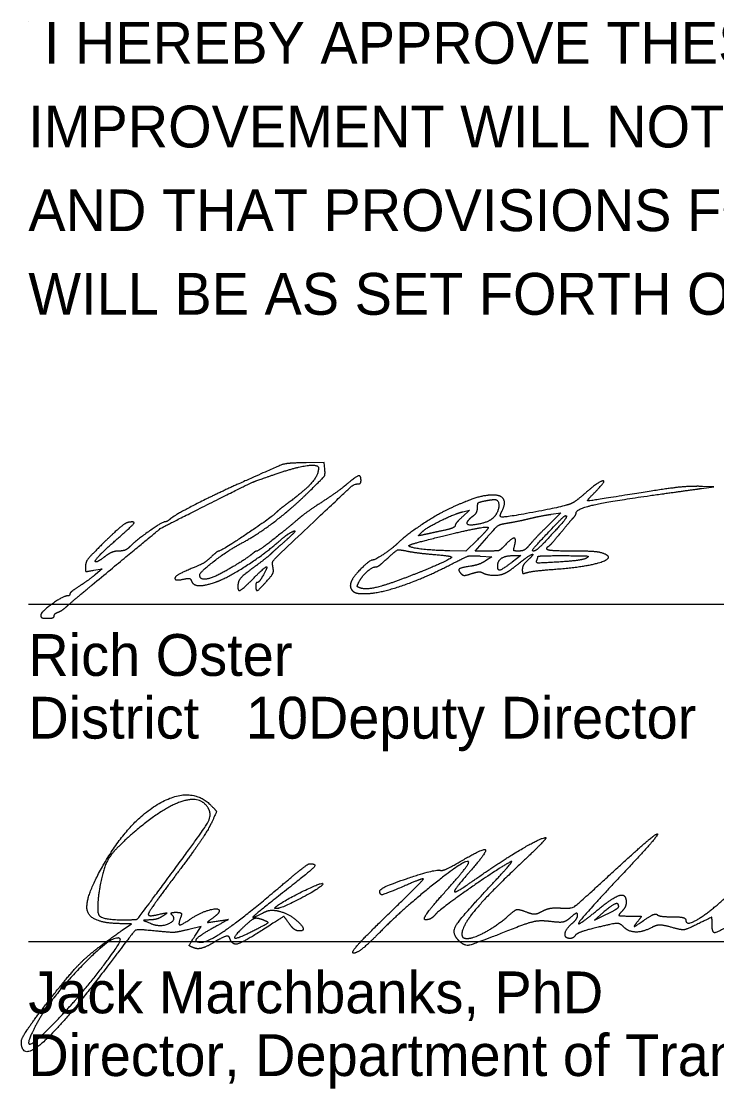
# Model space of a CAD drawing. Extents: x 0 to 34, y 0 to 22.
# Drawn here: x 24.504 to 26.833, y 7.305 to 10.877 of the extents above; entities that cross this region are included whole.
import ezdxf

# ---------------------------------------------------------------- set-up
doc = ezdxf.new("R2010")
doc.units = 0
doc.layers.add('SH_Data', color=7, linetype='Continuous')
doc.layers.add('SH_Text', color=7, linetype='Continuous')

msp = doc.modelspace()

# ---------------------------------------------------------------- linework, layer by layer
at = {"layer": 'SH_Data'}
for p, q in [((24.5279, 10.875), (24.5279, 10.875)), ((24.5279, 8.9262), (28.0279, 8.9262)), ((24.5279, 7.7968), (28.0279, 7.7968))]:
    msp.add_line(p, q, dxfattribs=at)
at = {"layer": 'SH_Text'}
for p, q in [((24.5693, 8.8891), (24.5693, 8.8891)), ((24.9902, 8.0019), (24.9902, 8.0019)), ((25.3555, 7.912), (25.3555, 7.912)), ((26.5045, 7.914), (26.5045, 7.914)), ((25.3107, 7.8703), (25.3107, 7.8703)), ((25.7273, 7.883), (25.7273, 7.883))]:
    msp.add_line(p, q, dxfattribs=at)
for points in [[(25.5205, 9.3784), (25.518, 9.4002), (25.458, 9.3995)], [(26.7818, 9.3137), (26.823, 9.3195), (26.7853, 9.3205)], [(25.9831, 9.2356), (26.0055, 9.2409), (25.9812, 9.2186)], [(26.2781, 9.2271), (26.3106, 9.2318), (26.2668, 9.1885)], [(26.0643, 9.104), (26.0234, 9.104), (26.0626, 9.1485)], [(26.0316, 9.1419), (25.9924, 9.104), (25.9389, 9.1049)], [(26.0409, 9.0875), (26.0801, 9.0852), (26.0587, 9.0712)], [(26.1518, 9.089), (26.177, 9.089), (26.1475, 9.0667)], [(24.7474, 9.0398), (24.7755, 9.0447), (24.753, 9.0259)], [(26.4527, 7.8943), (26.4232, 7.8687), (26.4638, 7.8884)], [(24.8425, 7.8349), (24.8732, 7.8561), (24.8354, 7.8568)], [(25.0855, 7.8151), (25.1067, 7.8474), (25.0649, 7.8373)]]:
    msp.add_lwpolyline(points, dxfattribs=at)
for points in [[(25.458, 9.3995), (25.3955, 9.3988), (25.3691, 9.3906), (25.233, 9.3295)], [(25.1505, 9.2712), (25.2627, 9.3275), (25.2883, 9.3388), (25.3605, 9.3634)], [(25.3605, 9.3634), (25.4246, 9.3853), (25.4993, 9.3953), (25.4993, 9.382)], [(25.4993, 9.382), (25.4993, 9.3581), (25.4543, 9.3067), (25.3951, 9.2632)], [(25.4605, 9.2959), (25.5145, 9.3482), (25.5227, 9.3595), (25.5205, 9.3784)], [(25.233, 9.3295), (25.1528, 9.2934), (25.017, 9.2238), (25.0037, 9.212)], [(25.3754, 9.0998), (25.5968, 9.3094), (25.6188, 9.3289), (25.6324, 9.3289)], [(25.5925, 9.3265), (25.5763, 9.3128), (25.5394, 9.2864), (25.5105, 9.2677)], [(25.6418, 9.3402), (25.6418, 9.3582), (25.6242, 9.3533), (25.5925, 9.3265)], [(25.6324, 9.3289), (25.6376, 9.3289), (25.6418, 9.334), (25.6418, 9.3402)], [(26.4286, 9.3046), (26.4654, 9.3414), (26.4359, 9.3361), (26.3929, 9.2981)], [(25.2372, 9.128), (25.2909, 9.1564), (25.4056, 9.2426), (25.4605, 9.2959)], [(26.0844, 9.2915), (26.0569, 9.2915), (25.9951, 9.2723), (25.9396, 9.2466)], [(26.1144, 9.2392), (26.1272, 9.2631), (26.1109, 9.2915), (26.0844, 9.2915)], [(26.3929, 9.2981), (26.3737, 9.2812), (26.3513, 9.2648), (26.343, 9.2618)], [(26.3618, 9.2311), (26.3618, 9.2455), (26.4844, 9.2727), (26.6551, 9.2961)], [(26.5253, 9.2906), (26.4049, 9.2711), (26.3963, 9.2723), (26.4286, 9.3046)], [(26.7853, 9.3205), (26.7409, 9.3216), (26.657, 9.312), (26.5253, 9.2906)], [(26.6551, 9.2961), (26.7021, 9.3026), (26.7591, 9.3105), (26.7818, 9.3137)], [(24.7418, 8.991), (24.9664, 9.177), (24.9759, 9.1835), (25.1505, 9.2712)], [(25.3951, 9.2632), (25.3802, 9.2522), (25.3621, 9.2373), (25.3548, 9.2301)], [(25.5105, 9.2677), (25.4817, 9.2491), (25.4479, 9.2251), (25.4355, 9.2145)], [(26.0318, 9.2497), (26.0318, 9.2632), (26.0371, 9.2681), (26.0552, 9.2718)], [(26.0552, 9.2718), (26.0681, 9.2743), (26.0833, 9.2765), (26.089, 9.2765)], [(26.089, 9.2765), (26.104, 9.2765), (26.102, 9.2337), (26.0862, 9.217)], [(26.343, 9.2618), (26.3157, 9.2517), (26.1139, 9.2143), (26.1097, 9.2185)], [(25.3548, 9.2301), (25.34, 9.2152), (25.1732, 9.104), (25.1659, 9.104)], [(25.9396, 9.2466), (25.8976, 9.2272), (25.7891, 9.1548), (25.7634, 9.1291)], [(25.8443, 9.1662), (25.8587, 9.1811), (25.9538, 9.2286), (25.9831, 9.2356)], [(25.9812, 9.2186), (25.9678, 9.2064), (25.9568, 9.193), (25.9568, 9.1888)], [(25.9985, 9.2025), (26.0019, 9.2081), (26.0107, 9.2171), (26.0182, 9.2225)], [(26.0182, 9.2225), (26.0257, 9.2279), (26.0318, 9.2401), (26.0318, 9.2497)], [(26.1097, 9.2185), (26.1074, 9.2208), (26.1096, 9.2301), (26.1144, 9.2392)], [(26.2043, 9.2126), (26.227, 9.218), (26.2602, 9.2245), (26.2781, 9.2271)], [(26.3288, 9.222), (26.3322, 9.2185), (26.3084, 9.1895), (26.2558, 9.1331)], [(26.3042, 9.2034), (26.3158, 9.2155), (26.3268, 9.2239), (26.3288, 9.222)], [(26.3524, 9.2151), (26.3576, 9.2206), (26.3618, 9.2277), (26.3618, 9.2311)], [(24.8621, 9.2001), (24.8541, 9.1988), (24.8186, 9.1694), (24.7834, 9.1349)], [(24.8524, 9.1685), (24.8801, 9.1927), (24.8835, 9.2036), (24.8621, 9.2001)], [(24.9846, 9.2015), (24.9759, 9.2015), (24.8862, 9.1376), (24.8671, 9.1179)], [(25.0037, 9.212), (24.9972, 9.2062), (24.9886, 9.2015), (24.9846, 9.2015)], [(25.4355, 9.2145), (25.3909, 9.1761), (25.2982, 9.104), (25.2935, 9.104)], [(25.8571, 9.1396), (25.9539, 9.1644), (26.0634, 9.1873), (26.0672, 9.1835)], [(25.9568, 9.1888), (25.9568, 9.1847), (25.9374, 9.1771), (25.9137, 9.172)], [(26.0862, 9.217), (26.0698, 9.1997), (25.9888, 9.1863), (25.9985, 9.2025)], [(26.0672, 9.1835), (26.0692, 9.1816), (26.0531, 9.1628), (26.0316, 9.1419)], [(26.0626, 9.1485), (26.095, 9.1853), (26.1072, 9.1939), (26.1324, 9.1979)], [(26.1324, 9.1979), (26.1493, 9.2005), (26.1816, 9.2071), (26.2043, 9.2126)], [(26.2668, 9.1885), (26.2428, 9.1646), (26.2155, 9.1359), (26.2062, 9.1245)], [(26.2196, 9.104), (26.2118, 9.104), (26.2332, 9.1291), (26.3042, 9.2034)], [(26.3093, 9.164), (26.3278, 9.1866), (26.3472, 9.2097), (26.3524, 9.2151)], [(24.7524, 9.0683), (24.7487, 9.072), (24.7956, 9.119), (24.8524, 9.1685)], [(25.3643, 9.1342), (25.3787, 9.1469), (25.3969, 9.1608), (25.4046, 9.1651)], [(25.4046, 9.1651), (25.4253, 9.1767), (25.4127, 9.159), (25.3802, 9.1307)], [(25.8518, 9.1586), (25.835, 9.155), (25.8342, 9.1558), (25.8443, 9.1662)], [(25.9137, 9.172), (25.8899, 9.1669), (25.8621, 9.1608), (25.8518, 9.1586)], [(26.1562, 9.1227), (26.1624, 9.1474), (26.1464, 9.1474), (26.1229, 9.1226)], [(26.2699, 9.1202), (26.273, 9.1216), (26.2907, 9.1413), (26.3093, 9.164)], [(24.7834, 9.1349), (24.737, 9.0894), (24.7193, 9.0669), (24.7193, 9.0534)], [(24.8671, 9.1179), (24.8597, 9.1102), (24.8435, 9.104), (24.831, 9.104)], [(25.1018, 9.024), (25.1018, 9.0335), (25.1976, 9.1071), (25.2372, 9.128)], [(25.155, 9.0002), (25.1921, 9.013), (25.3186, 9.094), (25.3643, 9.1342)], [(25.3802, 9.1307), (25.3656, 9.1181), (25.348, 9.1022), (25.3411, 9.0955)], [(25.7634, 9.1291), (25.7481, 9.1138), (25.6888, 9.074), (25.6813, 9.074)], [(25.8022, 9.121), (25.8002, 9.123), (25.8249, 9.1314), (25.8571, 9.1396)], [(25.9389, 9.1049), (25.8837, 9.1059), (25.8085, 9.1147), (25.8022, 9.121)], [(26.1229, 9.1226), (26.1083, 9.1072), (26.0981, 9.104), (26.0643, 9.104)], [(26.1704, 9.104), (26.154, 9.104), (26.1521, 9.1064), (26.1562, 9.1227)], [(26.2062, 9.1245), (26.1959, 9.112), (26.182, 9.104), (26.1704, 9.104)], [(26.2558, 9.1331), (26.2408, 9.1171), (26.2245, 9.104), (26.2196, 9.104)], [(26.2643, 9.1108), (26.2643, 9.1146), (26.2668, 9.1188), (26.2699, 9.1202)], [(26.3449, 9.1038), (26.3006, 9.1039), (26.2643, 9.107), (26.2643, 9.1108)], [(24.7823, 9.0842), (24.7681, 9.0733), (24.7546, 9.0661), (24.7524, 9.0683)], [(24.831, 9.104), (24.818, 9.104), (24.7972, 9.0955), (24.7823, 9.0842)], [(25.1409, 9.0852), (25.1217, 9.0674), (25.1072, 9.0594), (25.0512, 9.0356)], [(25.1659, 9.104), (25.1633, 9.104), (25.152, 9.0955), (25.1409, 9.0852)], [(25.2796, 9.0963), (25.265, 9.084), (25.2172, 9.0535), (25.1804, 9.033)], [(25.2935, 9.104), (25.2908, 9.104), (25.2846, 9.1005), (25.2796, 9.0963)], [(25.3411, 9.0955), (25.3342, 9.0888), (25.3097, 9.0693), (25.2867, 9.0523)], [(25.347, 9.0502), (25.3441, 9.0655), (25.3498, 9.0755), (25.3754, 9.0998)], [(25.7135, 9.0647), (25.7577, 9.1049), (25.7686, 9.11), (25.7974, 9.1038)], [(25.9443, 9.0819), (25.9348, 9.0738), (25.8329, 9.03), (25.7693, 9.0066)], [(25.7974, 9.1038), (25.8129, 9.1005), (25.8537, 9.0954), (25.8881, 9.0925)], [(25.8881, 9.0925), (25.9225, 9.0896), (25.9478, 9.0849), (25.9443, 9.0819)], [(25.9586, 9.0673), (25.9934, 9.0855), (26.0091, 9.0893), (26.0409, 9.0875)], [(26.0993, 9.054), (26.0993, 9.0714), (26.1257, 9.089), (26.1518, 9.089)], [(26.1728, 9.0645), (26.2054, 9.0909), (26.2247, 9.0955), (26.1968, 9.0702)], [(26.2304, 9.0726), (26.2326, 9.0781), (26.2343, 9.0841), (26.2343, 9.0858)], [(26.2343, 9.0858), (26.2343, 9.0875), (26.2739, 9.0888), (26.3224, 9.0887)], [(26.2943, 9.0436), (26.4055, 9.0522), (26.4942, 9.0854), (26.4427, 9.0991)], [(26.3965, 9.0804), (26.3888, 9.0759), (26.3474, 9.07), (26.3045, 9.0674)], [(26.3224, 9.0887), (26.3895, 9.0885), (26.4072, 9.0865), (26.3965, 9.0804)], [(26.4427, 9.0991), (26.4333, 9.1017), (26.3893, 9.1038), (26.3449, 9.1038)], [(24.7193, 9.0534), (24.7193, 9.036), (24.7211, 9.0351), (24.7474, 9.0398)], [(25.2867, 9.0523), (25.2468, 9.0228), (25.2293, 9.0021), (25.2293, 8.9844)], [(25.2792, 9.0102), (25.3176, 9.0491), (25.3317, 9.0538), (25.3133, 9.0215)], [(25.3267, 9.0037), (25.3443, 9.0238), (25.3497, 9.0361), (25.347, 9.0502)], [(25.6813, 9.074), (25.6704, 9.074), (25.6133, 9.0155), (25.608, 8.9989)], [(25.6353, 9.0014), (25.645, 9.0202), (25.6793, 9.0508), (25.691, 9.0512)], [(25.6524, 8.9615), (25.702, 8.9615), (25.8613, 9.0165), (25.9586, 9.0673)], [(25.691, 9.0512), (25.6954, 9.0513), (25.7055, 9.0574), (25.7135, 9.0647)], [(26.0081, 9.0533), (25.9766, 9.0491), (25.9656, 9.0397), (25.9778, 9.0275)], [(26.0587, 9.0712), (26.0469, 9.0635), (26.0241, 9.0555), (26.0081, 9.0533)], [(26.1475, 9.0667), (26.1155, 9.0425), (26.0993, 9.0382), (26.0993, 9.054)], [(26.1255, 9.0309), (26.1338, 9.035), (26.1551, 9.0502), (26.1728, 9.0645)], [(26.1968, 9.0702), (26.1886, 9.0628), (26.1818, 9.05), (26.1818, 9.0419)], [(26.1818, 9.0419), (26.1818, 9.0301), (26.1851, 9.0282), (26.1987, 9.0324)], [(26.1987, 9.0324), (26.2079, 9.0352), (26.251, 9.0403), (26.2943, 9.0436)], [(26.3045, 9.0674), (26.241, 9.0634), (26.2273, 9.0644), (26.2304, 9.0726)], [(24.753, 9.0259), (24.7407, 9.0155), (24.7162, 8.9978), (24.6987, 8.9865)], [(25.0512, 9.0356), (25.0199, 9.0224), (25.0178, 9.0033), (25.0483, 9.01)], [(25.0483, 9.01), (25.064, 9.0134), (25.0711, 9.0116), (25.0744, 9.0031)], [(25.0744, 9.0031), (25.0798, 8.989), (25.1185, 8.9877), (25.155, 9.0002)], [(25.1804, 9.033), (25.1433, 9.0123), (25.1018, 9.0075), (25.1018, 9.024)], [(25.2293, 8.9844), (25.2293, 8.9683), (25.2468, 8.9773), (25.2792, 9.0102)], [(25.2893, 8.9877), (25.2893, 8.9695), (25.3011, 8.9746), (25.3267, 9.0037)], [(25.3133, 9.0215), (25.3063, 9.0091), (25.298, 8.999), (25.2949, 8.999)], [(25.7693, 9.0066), (25.712, 8.9856), (25.653, 8.9744), (25.6362, 8.9813)], [(25.9778, 9.0275), (25.983, 9.0223), (25.994, 9.0227), (26.0122, 9.0287)], [(26.0122, 9.0287), (26.0269, 9.0335), (26.0429, 9.0351), (26.0476, 9.0322)], [(26.0476, 9.0322), (26.0617, 9.0235), (26.1094, 9.0227), (26.1255, 9.0309)], [(24.6593, 8.9212), (24.6696, 8.9306), (24.7067, 8.962), (24.7418, 8.991)], [(24.6987, 8.9865), (24.6811, 8.9752), (24.6668, 8.9633), (24.6668, 8.96)], [(25.2949, 8.999), (25.2918, 8.999), (25.2893, 8.9939), (25.2893, 8.9877)], [(25.608, 8.9989), (25.6053, 8.9903), (25.6071, 8.9783), (25.6121, 8.9723)], [(25.6121, 8.9723), (25.6173, 8.966), (25.6342, 8.9615), (25.6524, 8.9615)], [(25.6362, 8.9813), (25.6291, 8.9842), (25.6289, 8.989), (25.6353, 9.0014)], [(24.6592, 8.954), (24.645, 8.954), (24.5693, 8.8994), (24.5693, 8.8891)], [(24.6668, 8.96), (24.6668, 8.9567), (24.6634, 8.954), (24.6592, 8.954)], [(24.6143, 8.8867), (24.6143, 8.8909), (24.6202, 8.8966), (24.6274, 8.8993)], [(24.6274, 8.8993), (24.6346, 8.902), (24.649, 8.9119), (24.6593, 8.9212)], [(24.5693, 8.8891), (24.5693, 8.8828), (24.5778, 8.879), (24.5918, 8.879)], [(24.5918, 8.879), (24.6042, 8.879), (24.6143, 8.8824), (24.6143, 8.8867)], [(24.7789, 8.0526), (24.8651, 8.203), (25.0732, 8.319), (25.1389, 8.2534)], [(25.1299, 8.2442), (25.104, 8.2862), (24.9779, 8.245), (24.8825, 8.1634)], [(25.1389, 8.2534), (25.1577, 8.2346), (25.1577, 8.2295), (25.1394, 8.1911)], [(24.9902, 8.0019), (25.1115, 8.1653), (25.144, 8.2215), (25.1299, 8.2442)], [(25.1394, 8.1911), (25.1284, 8.1681), (25.0767, 8.0926), (25.0245, 8.0232)], [(24.8825, 8.1634), (24.8159, 8.1064), (24.7771, 8.0423), (24.766, 7.971)], [(26.4869, 8.0315), (26.5619, 8.1006), (26.6279, 8.1572), (26.6336, 8.1573)], [(26.6336, 8.1573), (26.6394, 8.1574), (26.5873, 8.0972), (26.518, 8.0236)], [(26.0326, 8.0111), (26.1131, 8.0677), (26.2445, 8.1449), (26.2602, 8.1449)], [(26.2602, 8.1449), (26.265, 8.1449), (26.2237, 8.1023), (26.1684, 8.0502)], [(25.9736, 8.0646), (26.0524, 8.1108), (26.0646, 8.0975), (26.0054, 8.0302)], [(24.8354, 7.8568), (24.7375, 7.8585), (24.7141, 7.9396), (24.7789, 8.0526)], [(25.369, 7.9791), (25.4194, 8.022), (25.4649, 8.0571), (25.4701, 8.0573)], [(25.4701, 8.0573), (25.495, 8.0578), (25.4716, 8.0322), (25.3857, 7.9649)], [(26.0017, 8.0644), (25.9921, 8.074), (25.7824, 7.907), (25.7045, 7.8278)], [(26.142, 8.0639), (26.0929, 8.0361), (25.9046, 7.9039), (25.8914, 7.888)], [(25.908, 8.0354), (25.9136, 8.0335), (25.9431, 8.0467), (25.9736, 8.0646)], [(25.9239, 7.964), (25.9702, 8.0157), (26.0052, 8.0609), (26.0017, 8.0644)], [(26.1684, 8.0502), (26.0687, 7.9565), (25.9795, 7.8484), (25.9795, 7.8214)], [(26.0768, 7.985), (26.123, 8.0342), (26.1523, 8.0697), (26.142, 8.0639)], [(25.0245, 8.0232), (24.9722, 7.9539), (24.9295, 7.8932), (24.9295, 7.8884)], [(25.7047, 7.9668), (25.7049, 7.9774), (25.8923, 8.0405), (25.908, 8.0354)], [(25.7273, 7.883), (25.7983, 7.9514), (25.8537, 8.0074), (25.8502, 8.0074)], [(25.8502, 8.0074), (25.8468, 8.0074), (25.8178, 7.9962), (25.7857, 7.9824)], [(26.0054, 8.0302), (25.9774, 7.9984), (25.9545, 7.9687), (25.9545, 7.9643)], [(25.9545, 7.9643), (25.9545, 7.9598), (25.9896, 7.9809), (26.0326, 8.0111)], [(26.3119, 7.9091), (26.3453, 7.9063), (26.3688, 7.9227), (26.4869, 8.0315)], [(26.518, 8.0236), (26.3885, 7.8861), (26.3564, 7.8388), (26.4386, 7.9065)], [(24.766, 7.971), (24.7545, 7.8977), (24.776, 7.8699), (24.844, 7.8699)], [(24.844, 7.8699), (24.8907, 7.8699), (24.8953, 7.874), (24.9902, 8.0019)], [(25.1076, 7.7949), (25.1307, 7.7949), (25.2567, 7.8837), (25.369, 7.9791)], [(25.3555, 7.912), (25.3759, 7.9299), (25.5079, 7.9956), (25.5131, 7.9905)], [(25.5131, 7.9905), (25.5193, 7.9843), (25.3767, 7.9074), (25.359, 7.9074)], [(25.7857, 7.9824), (25.7231, 7.9556), (25.7044, 7.952), (25.7047, 7.9668)], [(25.9697, 7.7993), (25.9445, 7.8246), (25.9734, 7.8747), (26.0768, 7.985)], [(26.7295, 7.8684), (26.7295, 7.8456), (26.8248, 7.907), (26.8951, 7.9753)], [(25.3857, 7.9649), (25.2925, 7.8919), (25.271, 7.8704), (25.315, 7.8939)], [(25.8581, 7.8699), (25.8478, 7.8699), (25.8767, 7.9112), (25.9239, 7.964)], [(26.4386, 7.9065), (26.487, 7.9464), (26.5295, 7.9568), (26.5295, 7.9287)], [(25.0736, 7.8743), (25.1025, 7.8941), (25.167, 7.9116), (25.167, 7.8997)], [(25.167, 7.8997), (25.167, 7.8952), (25.1572, 7.8843), (25.1453, 7.8756)], [(25.315, 7.8939), (25.3276, 7.9006), (25.3515, 7.9027), (25.3681, 7.8985)], [(25.359, 7.9074), (25.3542, 7.9074), (25.3526, 7.9095), (25.3555, 7.912)], [(25.3681, 7.8985), (25.4042, 7.8894), (25.4625, 7.8324), (25.4358, 7.8324)], [(26.137, 7.885), (26.1573, 7.903), (26.1701, 7.9056), (26.1939, 7.8966)], [(26.1939, 7.8966), (26.2141, 7.8889), (26.2329, 7.8896), (26.2489, 7.8987)], [(26.2489, 7.8987), (26.2623, 7.9062), (26.2906, 7.9109), (26.3119, 7.9091)], [(26.5045, 7.914), (26.5045, 7.9275), (26.4804, 7.9183), (26.4527, 7.8943)], [(26.4638, 7.8884), (26.4862, 7.8992), (26.5045, 7.9107), (26.5045, 7.914)], [(26.5145, 7.8974), (26.5028, 7.8858), (26.5087, 7.8824), (26.541, 7.8824)], [(26.5295, 7.9287), (26.5295, 7.9198), (26.5227, 7.9057), (26.5145, 7.8974)], [(24.9357, 7.8693), (24.9133, 7.8685), (24.9138, 7.8671), (24.9399, 7.8567)], [(24.9295, 7.8884), (24.9295, 7.8836), (24.9449, 7.8833), (24.9638, 7.8877)], [(24.9795, 7.883), (24.9692, 7.876), (24.9495, 7.8699), (24.9357, 7.8693)], [(24.9399, 7.8567), (24.9698, 7.8447), (25.026, 7.8693), (25.0086, 7.8867)], [(24.9638, 7.8877), (24.9894, 7.8936), (24.9934, 7.8924), (24.9795, 7.883)], [(25.0086, 7.8867), (25.004, 7.8912), (25.0103, 7.8949), (25.0225, 7.8949)], [(25.0225, 7.8949), (25.037, 7.8949), (25.0422, 7.8885), (25.0375, 7.8762)], [(25.0375, 7.8762), (25.0285, 7.8529), (25.0414, 7.8523), (25.0736, 7.8743)], [(25.1453, 7.8756), (25.1264, 7.8618), (25.1284, 7.8605), (25.161, 7.8654)], [(25.161, 7.8654), (25.1977, 7.871), (25.1976, 7.8707), (25.1522, 7.8456)], [(25.3107, 7.8703), (25.2935, 7.8767), (25.277, 7.8716), (25.2576, 7.8538)], [(25.2826, 7.834), (25.329, 7.8577), (25.3325, 7.8623), (25.3107, 7.8703)], [(25.4011, 7.8571), (25.3843, 7.8812), (25.3822, 7.8807), (25.3165, 7.8384)], [(25.617, 7.7581), (25.6067, 7.7583), (25.6563, 7.8145), (25.7273, 7.883)], [(25.8914, 7.888), (25.8831, 7.878), (25.8682, 7.8699), (25.8581, 7.8699)], [(25.9975, 7.8074), (26.0192, 7.8074), (26.1006, 7.8527), (26.137, 7.885)], [(26.2749, 7.864), (26.2457, 7.8677), (26.2058, 7.8612), (26.1693, 7.8468)], [(26.3444, 7.8784), (26.3287, 7.8642), (26.3075, 7.8598), (26.2749, 7.864)], [(26.367, 7.8859), (26.367, 7.893), (26.3568, 7.8896), (26.3444, 7.8784)], [(26.3482, 7.8574), (26.3585, 7.866), (26.367, 7.8788), (26.367, 7.8859)], [(26.541, 7.8824), (26.5785, 7.8824), (26.5809, 7.8804), (26.5654, 7.8611)], [(26.5654, 7.8611), (26.5533, 7.8461), (26.5598, 7.8478), (26.5871, 7.8669)], [(26.5871, 7.8669), (26.6085, 7.8819), (26.6293, 7.891), (26.6332, 7.8871)], [(26.6332, 7.8871), (26.6371, 7.8831), (26.6604, 7.8799), (26.6849, 7.8799)], [(26.6849, 7.8799), (26.7094, 7.8799), (26.7295, 7.8748), (26.7295, 7.8684)], [(26.817, 7.8559), (26.817, 7.8788), (26.8159, 7.8788), (26.7698, 7.8559)], [(24.5916, 7.5927), (24.6692, 7.6932), (24.7493, 7.7705), (24.8425, 7.8349)], [(24.9237, 7.835), (24.8903, 7.8383), (24.8786, 7.8278), (24.8019, 7.7262)], [(25.0649, 7.8373), (25.0246, 7.8276), (25.0023, 7.8272), (24.9237, 7.835)], [(25.1522, 7.8456), (25.1011, 7.8174), (25.0814, 7.7949), (25.1076, 7.7949)], [(25.3165, 7.8384), (25.2476, 7.794), (25.2101, 7.7843), (25.202, 7.8086)], [(25.2576, 7.8538), (25.2133, 7.8133), (25.2246, 7.8044), (25.2826, 7.834)], [(25.4358, 7.8324), (25.4262, 7.8324), (25.4106, 7.8435), (25.4011, 7.8571)], [(25.7045, 7.8278), (25.6667, 7.7893), (25.6273, 7.7579), (25.617, 7.7581)], [(26.1693, 7.8468), (26.0233, 7.7891), (25.9882, 7.7808), (25.9697, 7.7993)], [(26.3412, 7.8074), (26.3229, 7.8074), (26.3274, 7.8402), (26.3482, 7.8574)], [(26.4355, 7.8449), (26.3972, 7.8357), (26.3629, 7.8235), (26.3594, 7.8178)], [(26.5199, 7.847), (26.5088, 7.8582), (26.4887, 7.8577), (26.4355, 7.8449)], [(26.6162, 7.8445), (26.5854, 7.8281), (26.5376, 7.8293), (26.5199, 7.847)], [(26.6807, 7.8446), (26.6538, 7.8523), (26.6307, 7.8523), (26.6162, 7.8445)], [(26.7698, 7.8559), (26.7324, 7.8374), (26.7138, 7.8351), (26.6807, 7.8446)], [(26.8789, 7.8528), (26.8339, 7.8262), (26.817, 7.8271), (26.817, 7.8559)], [(24.8354, 7.8057), (24.8145, 7.8266), (24.596, 7.6009), (24.5497, 7.5106)], [(24.6198, 7.5293), (24.6874, 7.5984), (24.8431, 7.798), (24.8354, 7.8057)], [(25.0843, 7.775), (25.0661, 7.782), (25.0662, 7.7856), (25.0855, 7.8151)], [(25.1508, 7.7948), (25.1252, 7.7797), (25.0953, 7.7708), (25.0843, 7.775)], [(25.202, 7.8086), (25.1991, 7.8172), (25.1799, 7.812), (25.1508, 7.7948)], [(25.9795, 7.8214), (25.9795, 7.8137), (25.9876, 7.8074), (25.9975, 7.8074)], [(26.3594, 7.8178), (26.3559, 7.8121), (26.3477, 7.8074), (26.3412, 7.8074)], [(24.8019, 7.7262), (24.6496, 7.5241), (24.5045, 7.3955), (24.5045, 7.4625)], [(24.5045, 7.4625), (24.5045, 7.4721), (24.5437, 7.5307), (24.5916, 7.5927)], [(24.5497, 7.5106), (24.5184, 7.4496), (24.55, 7.4581), (24.6198, 7.5293)]]:
    msp.add_open_spline(points, degree=2, dxfattribs=at)

# ---------------------------------------------------------------- texts
at = {"layer": 'SH_Data'}
for s, p in [(' I HEREBY APPROVE THESE PLANS AND DECLARE THAT THE MAKING OF THIS', (24.5279, 10.735)), ('IMPROVEMENT WILL NOT REQUIRE THE CLOSING TO TRAFFIC OF THE HIGHWAY', (24.5279, 10.455)), ('AND THAT PROVISIONS FOR THE MAINTENANCE AND SAFETY OF TRAFFIC', (24.5279, 10.175)), ('WILL BE AS SET FORTH ON THE PLANS AND ESTIMATES.', (24.5279, 9.895))]:
    msp.add_text(s, height=0.14, dxfattribs=at).set_placement(p)
at = {"layer": 'SH_Text'}
for s, p in [('Rich Oster', (24.5279, 8.6862)), ('District       Deputy Director', (24.5279, 8.4762)), ('              10', (24.5279, 8.4762)), ('Jack Marchbanks, PhD', (24.5279, 7.5568)), ('Director, Department of Transportation', (24.5279, 7.3468))]:
    msp.add_text(s, height=0.14, dxfattribs=at).set_placement(p)

doc.saveas('drawing.dxf')
